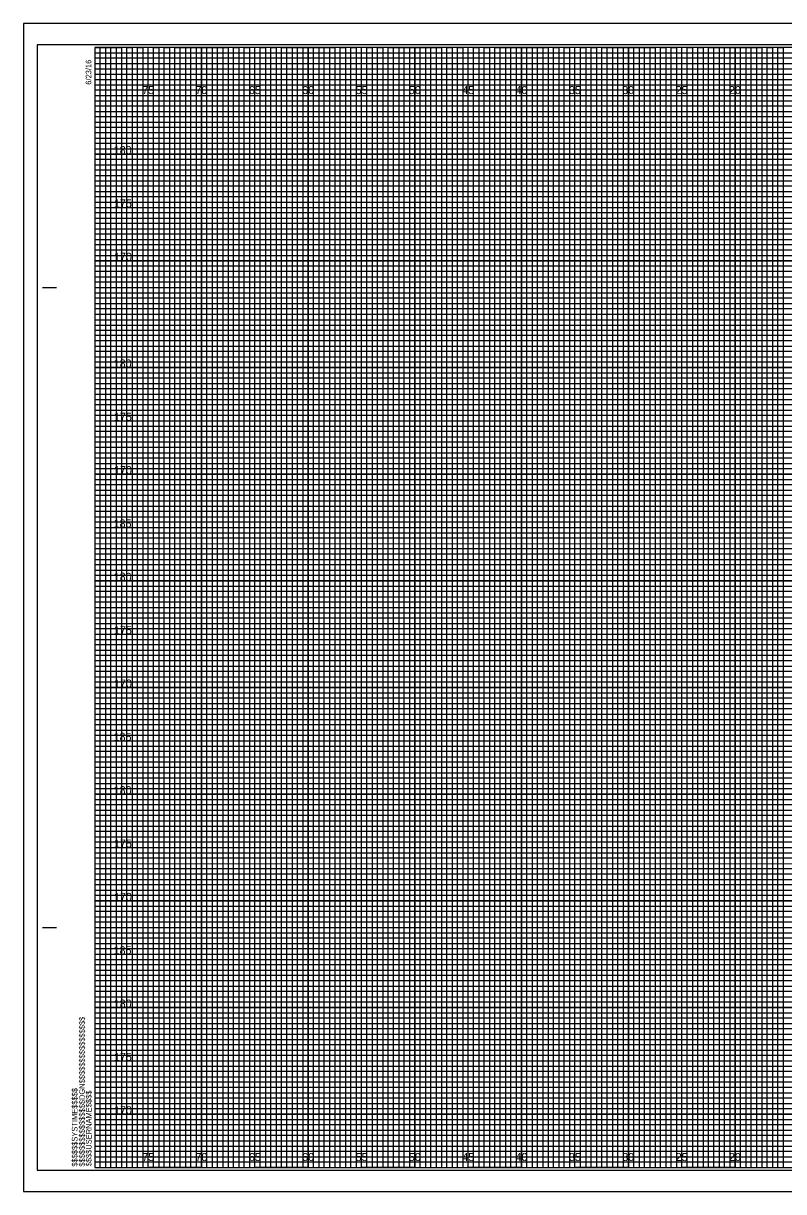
# Model space of a CAD drawing. Extents: x -7 to 162, y -2 to 767.
# Drawn here: x -6.7 to 64.6, y 547.8 to 657.2 of the extents above; entities that cross this region are included whole.
import ezdxf

# ---------------------------------------------------------------- set-up
doc = ezdxf.new("R2010")
doc.units = 0
for name, color, linetype in [('Exist Cross Section Cell', 7, 'Continuous'), ('Prop CMT Pvmt Course 1', 7, 'Continuous'), ('Prop CMT Pvmt Course 1 Wedge', 7, 'Continuous'), ('Prop CMT Pvmt Course 2', 7, 'Continuous'), ('Prop CMT Pvmt Course 3', 7, 'Continuous'), ('Prop CMT Pvmt Surface Shoulder', 7, 'Continuous'), ('Prop CMT Shld Paved Course 2', 7, 'Continuous'), ('Prop CMT Shld Paved Course 3', 7, 'Continuous'), ('Prop CMT Slope Grass', 7, 'Continuous'), ('Prop CMT Subgrade Earthwork', 7, 'Continuous'), ('Scratch_Level_0', 7, 'Continuous')]:
    doc.layers.add(name, color=color, linetype=linetype)

msp = doc.modelspace()

# ---------------------------------------------------------------- linework, layer by layer
at = {"layer": 'Prop CMT Pvmt Course 1'}
for p, q in [((0, 654.5), (130, 654.5)), ((130, 653.99), (0, 653.99)), ((0, 653.99), (0, 653.5)), ((0, 653.5), (130, 653.5)), ((130, 652.95), (0, 652.95)), ((0, 652.95), (0, 652)), ((0, 652), (160, 652))]:
    msp.add_line(p, q, dxfattribs=at)
for points in [[(0, 651.5), (135, 651.5), (160, 651.5), (160, 651), (0, 651)], [(0, 650.5), (160, 650.5), (160, 649.5), (0, 649.5)], [(0, 649), (160, 649), (160, 648.5), (0, 648.49)], [(0, 648), (160, 648), (160, 647), (0, 647)], [(0, 646.5), (160, 646.5), (160, 646), (0, 646)], [(0, 645.5), (160, 645.5), (160, 644.5), (0, 644.5)], [(0, 644), (160, 644), (160, 643.5), (0, 643.5)], [(0, 643), (160, 643), (160, 642), (0, 642)], [(0, 641.5), (160, 641.5), (160, 641), (0, 641)], [(0, 640.5), (160, 640.5), (160, 639.5), (0, 639.5)], [(0, 639), (160, 639), (160, 638.5), (0, 638.5)], [(0, 638), (160, 638), (160, 636.98), (160, 636.5), (160, 636), (0, 636)], [(0, 637), (160, 637), (160, 636.5), (0, 636.5)], [(0, 635.5), (160, 635.5), (160, 634.5), (0, 634.51)], [(0, 634.51), (160, 634.5), (160, 634), (0, 634)], [(0, 633.5), (160, 633.5), (160, 633), (0, 633)], [(0, 632), (160, 632), (160, 631.5), (0, 631.5)], [(0, 631), (160, 631), (160, 630.5), (0, 630.5)], [(-0.04, 629.45), (160, 629.45), (160, 628.94), (-0.04, 628.94)], [(0, 628.5), (160, 628.5), (160, 628), (0, 628)], [(0, 627), (160, 627), (160, 626.5), (0, 626.5)], [(0, 626), (160, 626), (160, 625.5), (0, 625.5)], [(0, 624.5), (160, 624.5), (160, 624), (0, 624)], [(0, 623.5), (160, 623.5), (160, 623), (0, 623)], [(0, 622), (160, 622), (160, 621.5), (0, 621.5)], [(0, 621), (160, 621), (160, 620.5), (0, 620.5)], [(0, 619.5), (160, 619.5), (160, 618.99), (0, 619)], [(0, 618.5), (160, 618.5), (160, 618), (0, 618)], [(0, 617), (160, 617), (160, 616.5), (0, 616.5)], [(0, 616), (160, 616), (160, 615.5), (0, 615.5)], [(0, 614.5), (160, 614.5), (160, 614), (0, 614)], [(0, 613.5), (160, 613.5), (160, 613), (0, 613)], [(0, 612), (160, 612), (160, 611.5), (0, 611.5)], [(0, 611), (160, 611), (160, 610.5), (0, 610.5)], [(0, 609.5), (160, 609.5), (160, 609), (0, 609)], [(0, 608.5), (160.03, 608.46), (160, 608), (0, 608)], [(0, 607), (160, 607), (160, 606.5), (0, 606.5)], [(0, 606), (160, 606), (160, 605.5), (0, 605.5)], [(0, 604.5), (160, 604.5), (160, 604), (0, 604)], [(0, 603.5), (160, 603.5), (160, 603), (0, 603)], [(0, 602), (160, 602), (160, 601.5), (0, 601.5)], [(0, 601), (160, 601), (160, 600.5), (0, 600.5)], [(0, 599.5), (160, 599.5), (160, 599), (0, 599)], [(0, 598.5), (160, 598.5), (160, 598), (0, 598)], [(0, 597), (160, 597), (160, 596.5), (0, 596.5)], [(0, 596), (160, 596), (160, 595.5), (0, 595.5)], [(0, 594.5), (160, 594.5), (160, 594), (0, 594)], [(0, 593.5), (160, 593.5), (160, 593), (0, 593)], [(0, 592), (160, 592), (160, 591.5), (0, 591.5)], [(0, 591), (160, 591), (160, 590.5), (0, 590.5)], [(0, 589.5), (160, 589.5), (160, 588.99), (0, 589)], [(0, 588.5), (160, 588.5), (160, 588), (0, 588)], [(0, 587), (160, 587), (160, 586.5), (0, 586.5)], [(0, 586), (160, 586), (160, 585.5), (0, 585.5)], [(0, 584.5), (160, 584.5), (160, 584), (0, 584)], [(0, 583.5), (160, 583.5), (160, 583), (0, 583)], [(0, 582), (160, 582), (160, 581.5), (0, 581.5)], [(0, 581), (160, 581), (160, 580.5), (0, 580.5)], [(0, 579.5), (160, 579.5), (160, 579), (0, 579)], [(0, 578.5), (160.03, 578.46), (160, 578), (0, 578)], [(0, 577), (160, 577), (160, 576.5), (0, 576.5)], [(0, 576), (160, 576), (160, 575.5), (0, 575.5)], [(0, 574.5), (160, 574.5), (160, 574), (0, 574)], [(0, 573.5), (160, 573.5), (160, 573), (0, 573)], [(0, 572), (160, 572), (160, 571.5), (0, 571.5)], [(0, 571), (160, 571), (160, 570.5), (0, 570.5)], [(0, 569.5), (160, 569.5), (160, 569), (0, 569)], [(0, 568.5), (160, 568.5), (160, 568), (0, 568)], [(0, 567), (160, 567), (160, 566.5), (0, 566.5)], [(0, 566), (160, 566), (160, 565.5), (0, 565.5)], [(0, 564.5), (160, 564.5), (160, 564), (0, 564)], [(0, 563.5), (160, 563.5), (160, 563), (0, 563)], [(0, 562), (160, 562), (160, 561.5), (0, 561.5)], [(0, 561), (160, 561), (160, 560.5), (0, 560.5)], [(0, 559.5), (160, 559.5), (160, 559), (0, 559)], [(0, 558.5), (160, 558.5), (160, 558), (0, 558)], [(0, 557), (160, 557), (160, 556.5), (0, 556.5)], [(0, 556), (160, 556), (160, 555.5), (0, 555.5)], [(0, 554.5), (160, 554.5), (160, 554), (0, 554)], [(0, 553.5), (160, 553.5), (160, 553), (0, 553)], [(0, 552), (160, 552), (160, 551.5), (0, 551.5)], [(0, 551), (160, 551), (160, 550.5), (0, 550.5)]]:
    msp.add_lwpolyline(points, dxfattribs=at)
at = {"layer": 'Prop CMT Pvmt Course 2'}
for p, q in [((5, 550), (5, 655)), ((10, 550), (10, 655)), ((15, 550), (15, 655)), ((20, 550), (20, 655)), ((25, 550), (25, 655)), ((30, 550), (30, 655)), ((35, 550), (35, 655)), ((40, 550), (40, 655)), ((45, 550), (45, 655)), ((50, 550), (50, 655)), ((55, 550), (55, 655)), ((60, 550), (60, 655)), ((0, 650), (160, 650)), ((0, 645), (160, 645)), ((0, 640), (160, 640)), ((0, 635), (160, 635)), ((0, 630), (160, 630)), ((0, 625), (160, 625)), ((0, 620), (160, 620)), ((0, 615), (160, 615)), ((0, 610), (160, 610)), ((0, 605), (160, 605)), ((0, 600), (160, 600)), ((0, 595), (160, 595)), ((0, 590), (160, 590)), ((0, 585), (160, 585)), ((0, 580), (160, 580)), ((0, 575), (160, 575)), ((0, 570), (160, 570)), ((0, 565), (160, 565)), ((0, 560), (160, 560)), ((0, 555), (160, 555))]:
    msp.add_line(p, q, dxfattribs=at)
at = {"layer": 'Prop CMT Pvmt Course 3'}
for p, q in [((161.65, 657.25), (-6.7, 657.25)), ((-6.7, 657.25), (-6.7, 547.75)), ((-6.7, 547.75), (161.65, 547.75))]:
    msp.add_line(p, q, dxfattribs=at)
at = {"layer": 'Prop CMT Pvmt Surface Shoulder'}
for points in [[(0, 655), (2.5, 655), (2.5, 550), (7.5, 550), (7.5, 655), (12.5, 655), (12.5, 550), (17.5, 550), (17.5, 655), (22.5, 655), (22.5, 550), (27.5, 550), (27.5, 655), (32.5, 655), (32.5, 550), (37.5, 550), (37.5, 655), (42.5, 655), (42.5, 550), (47.5, 550), (47.5, 655), (52.5, 655), (52.5, 550), (57.5, 550), (57.5, 655), (62.5, 655), (62.5, 550), (67.5, 550)], [(0, 652.5), (137.5, 652.5)], [(0, 642.5), (160, 642.5), (160, 647.5), (0, 647.5)], [(0, 632.5), (160, 632.5), (160, 637.5), (0, 637.5)], [(0, 622.5), (160, 622.5), (160, 627.5), (0, 627.5)], [(0, 612.5), (160, 612.5), (160, 617.5), (0, 617.5)], [(0, 602.5), (160, 602.5), (160, 607.5), (0, 607.5)], [(0, 592.5), (160, 592.5), (160, 597.5), (0, 597.5)], [(0, 582.5), (160, 582.5), (160, 587.5), (0, 587.5)], [(0, 572.5), (160, 572.5), (160, 577.5), (0, 577.5)], [(0, 562.5), (160, 562.5), (160, 567.5), (0, 567.5)], [(0, 552.5), (160, 552.5), (160, 557.5), (0, 557.5)]]:
    msp.add_lwpolyline(points, dxfattribs=at)
at = {"layer": 'Prop CMT Shld Paved Course 2'}
msp.add_lwpolyline([(-6.7, 547.75), (161.65, 547.75), (161.65, 657.25), (-6.7, 657.25)], close=True, dxfattribs=at)
at = {"layer": 'Prop CMT Shld Paved Course 3'}
msp.add_lwpolyline([(-5.4, 549.75), (161.2, 549.75), (161.2, 655.25), (-5.4, 655.25)], close=True, dxfattribs=at)
at = {"layer": 'Prop CMT Slope Grass'}
for points in [[(0, 550), (0.5, 550), (0.5, 655), (1, 655), (1, 550)], [(1, 550), (1.5, 550), (1.5, 655), (2, 655), (2, 550)], [(2.5, 550), (3, 550), (3, 655), (3.5, 655), (3.5, 550)], [(3.5, 550), (4, 550), (4, 655), (4.5, 655), (4.5, 550)], [(5, 550), (5.5, 550), (5.5, 655), (6, 655), (6, 550)], [(6, 550), (6.5, 550), (6.5, 655), (7, 655), (7, 550)], [(7.5, 550), (8, 550), (8, 655), (8.5, 655), (8.5, 550)], [(8.5, 550), (9, 550), (9, 655), (9.5, 655), (9.5, 550)], [(10, 550), (10.5, 550), (10.5, 655), (11, 655), (11, 550)], [(11, 550), (11.5, 550), (11.5, 655), (12, 655), (12, 550)], [(12.5, 550), (13, 550), (13, 655), (13.5, 655), (13.5, 550)], [(13.5, 550), (14, 550), (14, 655), (14.5, 655), (14.5, 550)], [(15, 550), (15.5, 550), (15.5, 655), (16, 655), (16, 550)], [(16, 550), (16.5, 550), (16.5, 655), (17, 655), (17, 550)], [(17.5, 550), (18, 550), (18, 655), (18.5, 655), (18.5, 550)], [(18.5, 550), (19, 550), (19, 655), (19.5, 655), (19.5, 550)], [(20, 550), (20.5, 550), (20.5, 655), (21, 655), (21, 550)], [(21, 550), (21.5, 550), (21.5, 655), (22, 655), (22, 550)], [(22.5, 550), (23, 550), (23, 655), (23.5, 655), (23.5, 550)], [(23.5, 550), (24, 550), (24, 655), (24.5, 655), (24.5, 550)], [(25, 550), (25.5, 550), (25.5, 655), (26, 655), (26, 550)], [(26, 550), (26.5, 550), (26.5, 655), (27, 655), (27, 550)], [(27.5, 550), (28, 550), (28, 655), (28.5, 655), (28.5, 550)], [(28.5, 550), (29, 550), (29, 655), (29.5, 655), (29.5, 550)], [(30, 550), (30.5, 550), (30.5, 655), (31, 655), (31, 550)], [(31, 550), (31.5, 550), (31.5, 655), (32, 655), (32, 550)], [(32.5, 550), (33, 550), (33, 655), (33.5, 655), (33.5, 550)], [(33.5, 550), (34, 550), (34, 655), (34.5, 655), (34.5, 550)], [(35, 550), (35.5, 550), (35.5, 655), (36, 655), (36, 550)], [(36, 550), (36.5, 550), (36.5, 655), (37, 655), (37, 550)], [(37.5, 550), (38, 550), (38, 655), (38.5, 655), (38.5, 550)], [(38.5, 550), (39, 550), (39, 655), (39.5, 655), (39.5, 550)], [(40, 550), (40.5, 550), (40.5, 655), (41, 655), (41, 550)], [(41, 550), (41.5, 550), (41.5, 655), (42, 655), (42, 550)], [(42.5, 550), (43, 550), (43, 655), (43.5, 655), (43.5, 550)], [(43.5, 550), (44, 550), (44, 655), (44.5, 655), (44.5, 550)], [(45, 550), (45.5, 550), (45.5, 655), (46, 655), (46, 550)], [(46, 550), (46.5, 550), (46.5, 655), (47, 655), (47, 550)], [(47.5, 550), (48, 550), (48, 655), (48.5, 655), (48.5, 550)], [(48.5, 550), (49, 550), (49, 655), (49.5, 655), (49.5, 550)], [(50, 550), (50.5, 550), (50.5, 655), (51, 655), (51, 550)], [(51, 550), (51.5, 550), (51.5, 655), (52, 655), (52, 550)], [(52.5, 550), (53, 550), (53, 655), (53.5, 655), (53.5, 550)], [(53.5, 550), (54, 550), (54, 655), (54.5, 655), (54.5, 550)], [(55, 550), (55.5, 550), (55.5, 655), (56, 655), (56, 550)], [(56, 550), (56.5, 550), (56.5, 655), (57, 655), (57, 550)], [(57.5, 550), (58, 550), (58, 655), (58.5, 655), (58.5, 550)], [(58.5, 550), (59, 550), (59, 655), (59.5, 655), (59.5, 550)], [(60, 550), (60.5, 550), (60.5, 655), (61, 655), (61, 550)], [(61, 550), (61.5, 550), (61.5, 655), (62, 655), (62, 550)], [(62.5, 550), (63, 550), (63, 655), (63.5, 655), (63.5, 550)], [(63.5, 550), (64, 550), (64, 655), (64.5, 655), (64.5, 550)]]:
    msp.add_lwpolyline(points, dxfattribs=at)
at = {"layer": 'Prop CMT Subgrade Earthwork'}
for p, q in [((-4.9, 632.5), (-3.65, 632.5)), ((-4.85, 632.5), (-3.6, 632.5)), ((-4.9, 572.5), (-3.65, 572.5)), ((-4.85, 572.5), (-3.6, 572.5)), ((0, 550), (0, 550)), ((0, 550), (0, 550)), ((0, 550), (0, 550)), ((0, 550), (0, 550)), ((0, 550), (0, 550)), ((0, 550), (0, 550)), ((0, 550), (0, 550))]:
    msp.add_line(p, q, dxfattribs=at)
msp.add_lwpolyline([(160, 655), (0, 655), (0, 550), (160, 550)], close=True, dxfattribs=at)
at = {"layer": 'Scratch_Level_0'}
for p, q in [((5, 655), (0, 655)), ((5, 550), (5, 655)), ((15, 655), (10, 655)), ((10, 655), (10, 550)), ((15, 550), (15, 655)), ((25, 655), (20, 655)), ((20, 655), (20, 550)), ((25, 550), (25, 655)), ((35, 655), (30, 655)), ((30, 655), (30, 550)), ((35, 550), (35, 655)), ((45, 655), (40, 655)), ((40, 655), (40, 550)), ((45, 550), (45, 655)), ((55, 655), (50, 655)), ((50, 655), (50, 550)), ((55, 550), (55, 655)), ((65, 655), (60, 655)), ((60, 655), (60, 550)), ((10, 550), (5, 550)), ((20, 550), (15, 550)), ((30, 550), (25, 550)), ((40, 550), (35, 550)), ((50, 550), (45, 550)), ((60, 550), (55, 550))]:
    msp.add_line(p, q, dxfattribs=at)
for points in [[(0, 650), (160, 650), (160, 645), (0, 645)], [(0, 640), (160, 640), (160, 635), (0, 635)], [(0, 630), (160, 630), (160, 625), (0, 625)], [(0, 620), (160, 620), (160, 615), (0, 615)], [(0, 610), (160, 610), (160, 605), (0, 605)], [(0, 600), (160, 600), (160, 595), (0, 595)], [(0, 590), (160, 590), (160, 585), (0, 585)], [(0, 580), (160, 580), (160, 575), (0, 575)], [(0, 570), (160, 570), (160, 565), (0, 565)], [(0, 560), (160, 560), (160, 555), (0, 555)]]:
    msp.add_lwpolyline(points, dxfattribs=at)

# ---------------------------------------------------------------- texts
at = {"layer": 'Exist Cross Section Cell'}
for s, p in [('75', (4.44, 650.62)), ('70', (9.43, 650.62)), ('65', (14.44, 650.62)), ('60', (19.43, 650.62)), ('55', (24.44, 650.62)), ('50', (29.43, 650.62)), ('45', (34.44, 650.62)), ('40', (39.43, 650.62)), ('35', (44.44, 650.62)), ('30', (49.43, 650.62)), ('25', (54.44, 650.62)), ('20', (59.43, 650.62)), ('75', (4.44, 550.62)), ('70', (9.43, 550.62)), ('65', (14.44, 550.62)), ('60', (19.43, 550.62)), ('55', (24.44, 550.62)), ('50', (29.43, 550.62)), ('45', (34.44, 550.62)), ('40', (39.43, 550.62)), ('35', (44.44, 550.62)), ('30', (49.43, 550.62)), ('25', (54.44, 550.62)), ('20', (59.43, 550.62))]:
    msp.add_text(s, height=0.75, dxfattribs=at).set_placement(p)
at = {"layer": 'Prop CMT Pvmt Course 1 Wedge'}
for s, p in [('180', (1.77, 645)), ('175', (1.79, 640)), ('170', (1.8, 635)), ('180', (1.77, 625)), ('175', (1.79, 620)), ('170', (1.8, 615)), ('185', (1.76, 610)), ('180', (1.77, 605)), ('175', (1.79, 600)), ('170', (1.8, 595)), ('185', (1.76, 590)), ('180', (1.77, 585)), ('175', (1.79, 580)), ('170', (1.8, 575)), ('185', (1.76, 570)), ('180', (1.77, 565)), ('175', (1.79, 560)), ('170', (1.8, 555))]:
    msp.add_text(s, height=0.75, dxfattribs=at).set_placement(p)
at = {"layer": 'Prop CMT Subgrade Earthwork'}
for s, p in [('6/23/16', (-0.33, 651.5)), ('$$$$$$$$$$$$$$$$DGN$$$$$$$$$$$$$$$$', (-0.94, 550.09)), ('$$$$$$SYSTIME$$$$$', (-1.63, 550.09)), ('$$$$USERNAME$$$$', (-0.31, 550.12))]:
    msp.add_text(s, height=0.525, rotation=90, dxfattribs=at).set_placement(p)

doc.saveas('drawing.dxf')
